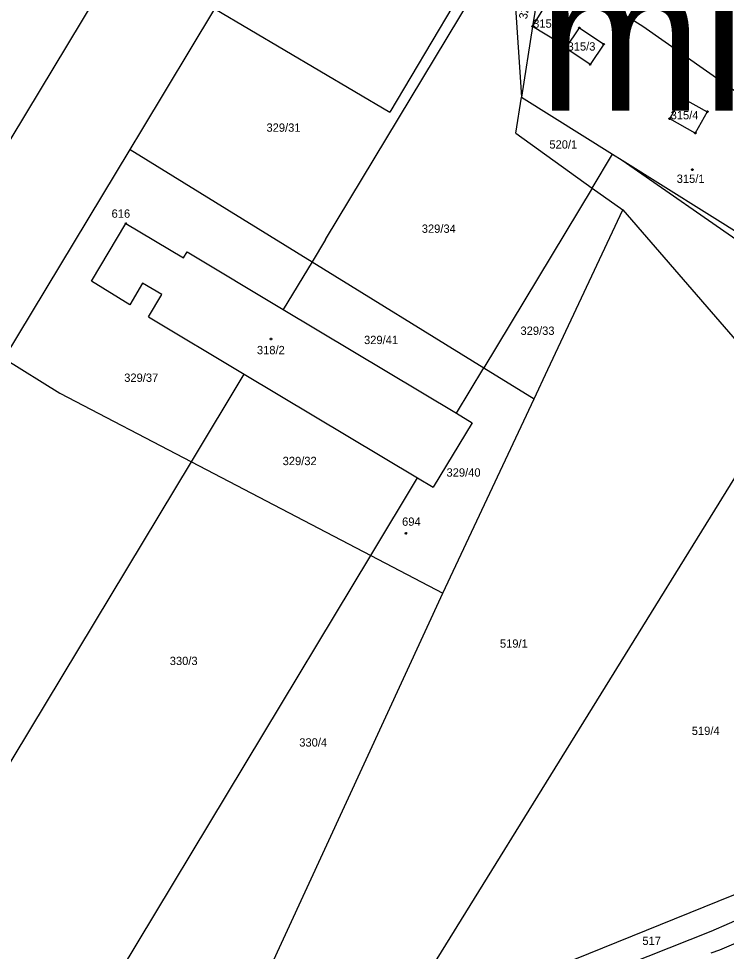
# Model space of a CAD drawing. Extents: x -634640 to -629202, y -1196156 to -1190068.
# Drawn here: x -632066.6 to -631922.1, y -1192813.3 to -1192622.8 of the extents above; entities that cross this region are included whole.
import ezdxf

# ---------------------------------------------------------------- set-up
doc = ezdxf.new("R2010")
doc.units = 0
for name, color, linetype in [('Obvod šetřený', 7, 'Continuous'), ('Vrstva 1', 7, 'Continuous'), ('Vrstva 2', 7, 'Continuous'), ('Vrstva 3', 7, 'Continuous'), ('Vrstva 5', 7, 'Continuous'), ('Vrstva 8', 7, 'Continuous')]:
    doc.layers.add(name, color=color, linetype=linetype)

msp = doc.modelspace()

# ---------------------------------------------------------------- linework, layer by layer
at = {"layer": 'Vrstva 1'}
for p, q in [((-632157.82, -1192795.99), (-632025.17, -1192575.82)), ((-632003.98, -1192667.9), (-631967.68, -1192607.65)), ((-631965.97, -1192608.47), (-631963.94, -1192638.83)), ((-631959.62, -1192611.5), (-631961.65, -1192624.34)), ((-631959.62, -1192611.5), (-631939.14, -1192624.27)), ((-632041.49, -1192645.56), (-632026.54, -1192620.75)), ((-632026.54, -1192620.75), (-631990.81, -1192641.85)), ((-631977.98, -1192620.18), (-631990.81, -1192641.85)), ((-631961.65, -1192624.34), (-631963.94, -1192638.83)), ((-631939.14, -1192624.27), (-631912.1, -1192643.29)), ((-631965.11, -1192646.19), (-631963.94, -1192638.83)), ((-631963.94, -1192638.83), (-631945.32, -1192650.48)), ((-632043.88, -1192649.52), (-632041.49, -1192645.56)), ((-631965.11, -1192646.19), (-631949.47, -1192657.37)), ((-632069.57, -1192692.18), (-632043.88, -1192649.52)), ((-632043.88, -1192649.52), (-632006.71, -1192672.43)), ((-631949.47, -1192657.37), (-631945.32, -1192650.48)), ((-631945.32, -1192650.48), (-631943.37, -1192651.7)), ((-631943.37, -1192651.7), (-631899.23, -1192682.4)), ((-631943.37, -1192651.7), (-631898.18, -1192679.98)), ((-631949.47, -1192657.37), (-631971.6, -1192694.09)), ((-631949.47, -1192657.37), (-631943.25, -1192661.82)), ((-631958.54, -1192694.41), (-631943.25, -1192661.82)), ((-631943.25, -1192661.82), (-631910.15, -1192700.05)), ((-632051.75, -1192676.41), (-632044.73, -1192664.63)), ((-632044.73, -1192664.63), (-632032.95, -1192671.66)), ((-632003.98, -1192667.9), (-632006.71, -1192672.43)), ((-632032.95, -1192671.66), (-632032.21, -1192670.41)), ((-632032.21, -1192670.41), (-632012.58, -1192682.18)), ((-632006.71, -1192672.43), (-632012.58, -1192682.18)), ((-632006.71, -1192672.43), (-631971.6, -1192694.09)), ((-632043.89, -1192681.22), (-632051.75, -1192676.41)), ((-632041.34, -1192676.79), (-632043.89, -1192681.22)), ((-632037.42, -1192679.13), (-632041.34, -1192676.79)), ((-632040.12, -1192683.66), (-632037.42, -1192679.13)), ((-632040.12, -1192683.66), (-632020.54, -1192695.39)), ((-632012.58, -1192682.18), (-631977.2, -1192703.38)), ((-632069.57, -1192692.18), (-632058.22, -1192699.27)), ((-632031.34, -1192713.31), (-632020.54, -1192695.39)), ((-632020.54, -1192695.39), (-631985.15, -1192716.58)), ((-631977.2, -1192703.38), (-631971.6, -1192694.09)), ((-631971.6, -1192694.09), (-631961.35, -1192700.41)), ((-631961.35, -1192700.41), (-631958.54, -1192694.41)), ((-632058.22, -1192699.27), (-632031.34, -1192713.31)), ((-632001.69, -1192847.96), (-631910.15, -1192700.05)), ((-631979.98, -1192740.13), (-631961.35, -1192700.41)), ((-631977.2, -1192703.38), (-631973.98, -1192705.31)), ((-631973.98, -1192705.31), (-631981.94, -1192718.5)), ((-632101.57, -1192829.88), (-632031.34, -1192713.31)), ((-632031.34, -1192713.31), (-631994.7, -1192732.44)), ((-631994.7, -1192732.44), (-631985.15, -1192716.58)), ((-631985.15, -1192716.58), (-631981.94, -1192718.5)), ((-632066.34, -1192851.34), (-631994.7, -1192732.44)), ((-631994.7, -1192732.44), (-631979.98, -1192740.13)), ((-632032.85, -1192854.81), (-631979.98, -1192740.13)), ((-631925.18, -1192809.17), (-631899.04, -1192797.87)), ((-631956.23, -1192816.21), (-631917.39, -1192800.45)), ((-631923.43, -1192812.98), (-631896.9, -1192801.74)), ((-631961.8, -1192823.68), (-631925.18, -1192809.17)), ((-631925.16, -1192813.64), (-631923.43, -1192812.98))]:
    msp.add_line(p, q, dxfattribs=at)
for points in [[(-631961.65, -1192624.34), (-631959.03, -1192620.07), (-631953.92, -1192623.21), (-631956.53, -1192627.47), (-631961.65, -1192624.34)], [(-631954.9, -1192628.78), (-631952.11, -1192624.63), (-631947.13, -1192627.99), (-631949.91, -1192632.14), (-631954.9, -1192628.78)], [(-631933.66, -1192643.21), (-631931.22, -1192638.84), (-631925.98, -1192641.77), (-631928.43, -1192646.13), (-631933.66, -1192643.21)]]:
    msp.add_lwpolyline(points, dxfattribs=at)
at = {"layer": 'Vrstva 3'}
msp.add_lwpolyline([(-631928.96, -1192653.47), (-631928.87, -1192653.62), (-631928.96, -1192653.77), (-631929.14, -1192653.77), (-631929.23, -1192653.62), (-631929.14, -1192653.47), (-631928.96, -1192653.47)], dxfattribs=at)
at = {"layer": 'Vrstva 5'}
msp.add_lwpolyline([(-632015, -1192688.06), (-632014.91, -1192688.21), (-632015, -1192688.36), (-632015.18, -1192688.36), (-632015.27, -1192688.21), (-632015.18, -1192688.06), (-632015, -1192688.06)], dxfattribs=at)
at = {"layer": 'Vrstva 8'}
for points in [[(-631953.83, -1192623.06), (-631953.74, -1192623.21), (-631953.83, -1192623.36), (-631954.01, -1192623.36), (-631954.1, -1192623.21), (-631954.01, -1192623.06), (-631953.83, -1192623.06)], [(-631961.56, -1192624.19), (-631961.47, -1192624.34), (-631961.56, -1192624.49), (-631961.74, -1192624.49), (-631961.83, -1192624.34), (-631961.74, -1192624.19), (-631961.56, -1192624.19)], [(-631952.02, -1192624.48), (-631951.93, -1192624.63), (-631952.02, -1192624.78), (-631952.2, -1192624.78), (-631952.29, -1192624.63), (-631952.2, -1192624.48), (-631952.02, -1192624.48)], [(-631956.44, -1192627.32), (-631956.35, -1192627.47), (-631956.44, -1192627.62), (-631956.62, -1192627.62), (-631956.71, -1192627.47), (-631956.62, -1192627.32), (-631956.44, -1192627.32)], [(-631954.81, -1192628.63), (-631954.72, -1192628.78), (-631954.81, -1192628.93), (-631954.99, -1192628.93), (-631955.08, -1192628.78), (-631954.99, -1192628.63), (-631954.81, -1192628.63)], [(-631947.04, -1192627.84), (-631946.95, -1192627.99), (-631947.04, -1192628.14), (-631947.22, -1192628.14), (-631947.31, -1192627.99), (-631947.22, -1192627.84), (-631947.04, -1192627.84)], [(-631949.82, -1192631.99), (-631949.73, -1192632.14), (-631949.82, -1192632.29), (-631950, -1192632.29), (-631950.09, -1192632.14), (-631950, -1192631.99), (-631949.82, -1192631.99)], [(-631931.13, -1192638.69), (-631931.04, -1192638.84), (-631931.13, -1192638.99), (-631931.31, -1192638.99), (-631931.4, -1192638.84), (-631931.31, -1192638.69), (-631931.13, -1192638.69)], [(-631925.89, -1192641.62), (-631925.8, -1192641.77), (-631925.89, -1192641.92), (-631926.07, -1192641.92), (-631926.16, -1192641.77), (-631926.07, -1192641.62), (-631925.89, -1192641.62)], [(-631933.57, -1192643.06), (-631933.48, -1192643.21), (-631933.57, -1192643.36), (-631933.75, -1192643.36), (-631933.84, -1192643.21), (-631933.75, -1192643.06), (-631933.57, -1192643.06)], [(-631928.34, -1192645.98), (-631928.25, -1192646.13), (-631928.34, -1192646.28), (-631928.52, -1192646.28), (-631928.61, -1192646.13), (-631928.52, -1192645.98), (-631928.34, -1192645.98)], [(-632044.64, -1192664.48), (-632044.55, -1192664.63), (-632044.64, -1192664.78), (-632044.82, -1192664.78), (-632044.91, -1192664.63), (-632044.82, -1192664.48), (-632044.64, -1192664.48)], [(-631987.45, -1192727.77), (-631987.36, -1192727.92), (-631987.45, -1192728.07), (-631987.63, -1192728.07), (-631987.72, -1192727.92), (-631987.63, -1192727.77), (-631987.45, -1192727.77)]]:
    msp.add_lwpolyline(points, dxfattribs=at)

# ---------------------------------------------------------------- texts
at = {"layer": 'Obvod šetřený'}
msp.add_text('mimo obvod KoPÚ', height=30, dxfattribs=at).set_placement((-631960.455, -1192641.53))
at = {"layer": 'Vrstva 2'}
msp.add_text('329/35', height=1.7, rotation=79.69843, dxfattribs=at).set_placement((-631962.818, -1192622.966))
for s, p in [('315/2', (-631961.54, -1192624.62)), ('315/3', (-631954.52, -1192629.29)), ('315/4', (-631933.471, -1192643.33)), ('329/31', (-632016.013, -1192645.87)), ('520/1', (-631958.233, -1192649.31)), ('315/1', (-631932.222, -1192656.32)), ('329/34', (-631984.293, -1192666.52)), ('329/33', (-631964.133, -1192687.37)), ('329/41', (-631996.09, -1192689.25)), ('318/2', (-632017.963, -1192691.32)), ('329/37', (-632045.073, -1192696.97)), ('329/32', (-632012.713, -1192713.98)), ('329/40', (-631979.242, -1192716.33)), ('519/1', (-631968.333, -1192751.28)), ('330/3', (-632035.773, -1192754.82)), ('519/4', (-631929.143, -1192769.1)), ('330/4', (-632009.313, -1192771.48)), ('517', (-631939.233, -1192812.01))]:
    msp.add_text(s, height=1.7, dxfattribs=at).set_placement(p)
at = {"layer": 'Vrstva 8'}
for s, p in [('616', (-632047.653, -1192663.44)), ('694', (-631988.313, -1192726.37))]:
    msp.add_text(s, height=1.7, dxfattribs=at).set_placement(p)

doc.saveas('drawing.dxf')
